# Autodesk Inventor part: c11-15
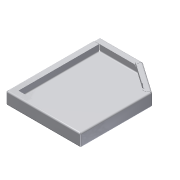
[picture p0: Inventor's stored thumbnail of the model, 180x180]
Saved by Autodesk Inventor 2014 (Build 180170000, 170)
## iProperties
Created: 2011-01
Part Number: c11-15
Material: Steel, Mild
Document SubType Name: Sheet Metal
Designer: Thom Tremblay
Density: 7.86 g/cm^3
Sheet Metal Rule: Steel - 16ga
Flat Pattern Width: 34.6788 cm
Flat Pattern Length: 40.6788 cm
Flat Pattern Area: 1410.69 cm^2
Sheet Metal Width: 346.788 mm
Sheet Metal Length: 406.788 mm
Sheet Metal Area: 141069.500 mm^2
Appearance: Ceramic
Author: Thom Tremblay
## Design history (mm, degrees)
node "Face1"
  sketch "Sketch1"
    geometry: L1 (0, 0)-(240, 0); L2 (240, 0)-(240, 300); L3 (240, 300)-(0, 300); L4 (0, 300)-(0, 0); L5 (140, 300)-(240, 229.979)
    constraints: 10 end point, 2 parallel, 2 point on line, 1 horizontal, 1 perpendicular
    dimensions: "d0" = 240 distance of L3.end L2.end; "d1" = 300 distance of L2.end L1.end; "d2" = 35 deg angle of L3 L5; "d3" = 100 distance from line of L2 L5.start
node "Flange1"
node "Flange2"
node "Flange3"
body "Solid1"
face "Plate1" dims "Thickness" = 1.524 (derived)
sketch "Sketch2"
  geometry: L1 through (-150, 0) direction (1, 0); L2 through (0, 20) direction (0, 1); L3 (0, 40)-(-300, 40); L4 (-300, 40)-(-300, 0)
  constraints: 6 end point, 1 horizontal, 1 perpendicular, 1 vertical
face "Plate2" dims "d5" = 1.524 (= BendReliefWidth), "d6" = 0.762 (= BendReliefDepth), "d7" = 3.048 (= MinimumRemnant), "d8" = 3.048 (= BendRadius), "d9" = 40, "d10" = 90 deg, "d11" = 3.048 (= BendRadius), "d12" = 6.096 (= CornerReliefSize), "d13" = 0.762 (= GapSize), "d14" = 3.048 (= JacobiRadiusSize), "SeamGap" = 0.01, "Thickness" = 1.524 (derived)
bend "Bend1" dims "d5" = 1.524 (= BendReliefWidth), "d6" = 0.762 (= BendReliefDepth), "d7" = 3.048 (= MinimumRemnant), "d8" = 3.048 (= BendRadius), "d9" = 40, "d10" = 90 deg, "d11" = 3.048 (= BendRadius), "SeamGap" = 0.01, "Thickness" = 1.524 (derived)
feature "Corner1" dims "d9" = 40, "d10" = 90 deg, "d12" = 6.096 (= CornerReliefSize), "d13" = 0.762 (= GapSize), "d14" = 3.048 (= JacobiRadiusSize)
sketch "Sketch3"
  geometry: L1 through (-117.937, 0) direction (1, 1.89e-49); L2 through (0, 10) direction (-3.49e-49, 1); L3 (0, 20)-(-235.874, 20); L4 (-235.874, 20)-(-235.874, 0)
  constraints: 6 end point, 1 horizontal, 1 perpendicular, 1 vertical
face "Plate3" dims "d15" = 1.524 (= BendReliefWidth), "d16" = 0.762 (= BendReliefDepth), "d17" = 3.048 (= MinimumRemnant), "d18" = 3.048 (= BendRadius), "d19" = 20, "d20" = 90 deg, "d21" = 3.048 (= BendRadius), "d22" = 6.096 (= CornerReliefSize), "d23" = 0.762 (= GapSize), "d24" = 3.048 (= JacobiRadiusSize), "d26" = 10, "SeamGap" = 0.01, "Thickness" = 1.524 (derived)
bend "Bend2" dims "d15" = 1.524 (= BendReliefWidth), "d16" = 0.762 (= BendReliefDepth), "d17" = 3.048 (= MinimumRemnant), "d18" = 3.048 (= BendRadius), "d19" = 20, "d20" = 90 deg, "d21" = 3.048 (= BendRadius), "SeamGap" = 0.01, "Thickness" = 1.524 (derived)
feature "Corner2" dims "d19" = 20, "d20" = 90 deg, "d22" = 6.096 (= CornerReliefSize), "d23" = 0.762 (= GapSize), "d24" = 3.048 (= JacobiRadiusSize)
sketch "Sketch4"
  geometry: L1 (-94.531, 0)-(-10, 0); L2 (-10, 0)-(-10, 15); L3 (-10, 15)-(-94.531, 15); L4 (-94.531, 15)-(-94.531, 0)
  constraints: 8 end point
face "Plate4" dims "d27" = 1.524 (= BendReliefWidth), "d28" = 0.762 (= BendReliefDepth), "d29" = 3.048 (= MinimumRemnant), "d30" = 3.048 (= BendRadius), "d31" = 10, "d32" = 10, "d33" = 15, "d34" = 90 deg, "d35" = 3.048 (= BendRadius), "d36" = 6.096 (= CornerReliefSize), "d37" = 0.762 (= GapSize), "d38" = 3.048 (= JacobiRadiusSize), "SeamGap" = 0.01, "Thickness" = 1.524 (derived)
bend "Bend3" dims "d27" = 1.524 (= BendReliefWidth), "d28" = 0.762 (= BendReliefDepth), "d29" = 3.048 (= MinimumRemnant), "d30" = 3.048 (= BendRadius), "d33" = 15, "d34" = 90 deg, "d35" = 3.048 (= BendRadius), "SeamGap" = 0.01, "Thickness" = 1.524 (derived)
feature "Corner3" dims "d33" = 15, "d34" = 90 deg, "d36" = 6.096 (= CornerReliefSize), "d37" = 0.762 (= GapSize), "d38" = 3.048 (= JacobiRadiusSize)
feature "Definition1"
fillet "Fillet1" dims "d0" = 5
fillet "Fillet2" dims "d1" = 5
fillet "Fillet3" dims "d2" = 5
fillet "Fillet4" dims "d3" = 2
fillet "Fillet5" dims "d4" = 2
other parameters: "BendRadius" = 3.048 (= 2 x Thickness), "BendReliefWidth" = 1.524 (= Thickness), "BendReliefDepth" = 0.762 (= 0.5 x Thickness), "CornerReliefSize" = 6.096 (= 4 x Thickness), "MinimumRemnant" = 3.048 (= 2 x Thickness), "TransitionRadius" = 3.048 (= BendRadius), "JacobiRadiusSize" = 3.048 (= BendRadius), "GapSize" = 0.762 (= 0.5 x Thickness), "d4" = 3.048 (= BendRadius), "BendRadius" = 3.048, "BendReliefDepth" = 0.762, "BendReliefWidth" = 1.524, "CornerReliefSize" = 6.096, "GapSize" = 0.762, "JacobiRadiusSize" = 3.048, "MinimumRemnant" = 3.048, "Thickness" = 1.524, "TransitionRadius" = 3.048
